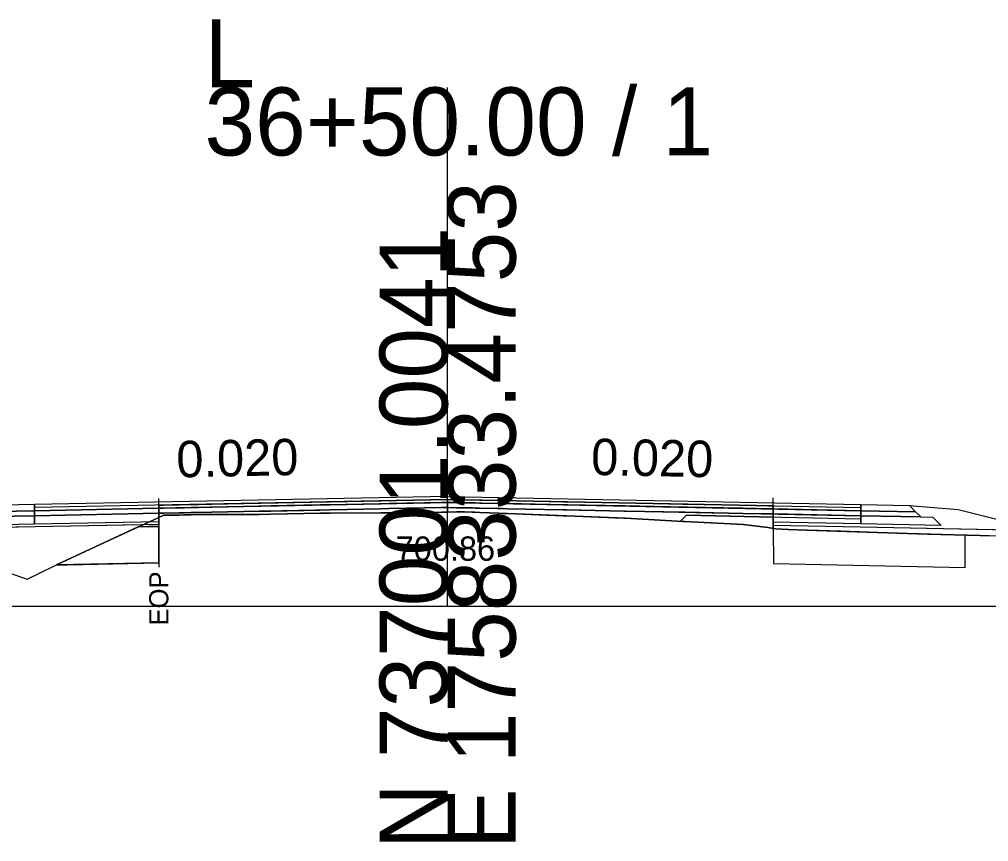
# Model space of a CAD drawing. Extents: x -26 to 4303, y -10 to 9577.
# Drawn here: x 2132.38 to 2172.26, y 6490.31 to 6524.14 of the extents above; entities that cross this region are included whole.
import ezdxf

# ---------------------------------------------------------------- set-up
doc = ezdxf.new("R2010")
doc.units = 0
for name, color, linetype in [('Exist CMT Pavement', 7, 'Continuous'), ('Old_Level_2', 7, 'Continuous'), ('Pattern 3', 7, 'Continuous'), ('Prop CMT Conc Surface', 7, 'Continuous'), ('Prop CMT Concrete Structures', 7, 'Continuous'), ('Prop CMT Pvmt Course 1', 7, 'Continuous'), ('Prop CMT Pvmt Course 1 CG', 7, 'Continuous'), ('Prop CMT Pvmt Course 1 Wedge', 7, 'Continuous'), ('Prop CMT Pvmt Course 2', 7, 'Continuous'), ('Prop CMT Pvmt Course 2 Wedge', 7, 'Continuous'), ('Prop CMT Pvmt Course 3', 7, 'Continuous'), ('Prop CMT Pvmt Surface', 7, 'Continuous'), ('Prop CMT Pvmt Surface Shoulder', 7, 'Continuous'), ('Prop CMT Pvmt Wedge Surface 1', 7, 'Continuous'), ('Prop CMT Pvmt Wedge Surface 2', 7, 'Continuous'), ('Prop CMT Pvmt Wedge Surface 3', 7, 'Continuous'), ('Prop CMT Shld Paved Course 1', 7, 'Continuous'), ('Prop CMT Shld Paved Course 2', 7, 'Continuous'), ('Prop CMT Shld Paved Course 3', 7, 'Continuous'), ('Prop CMT Slope Grass', 7, 'Continuous'), ('Prop CMT Subgrade Earthwork', 7, 'Continuous'), ('Prop Road Sect_ Recs - UC Shallow (Outline)', 7, 'Continuous'), ('Prop Shade Light', 7, 'Continuous'), ('Prop XS DDE Elevations', 7, 'Continuous'), ('Prop XS Ditch Standard Text', 7, 'Continuous'), ('Prop XS SE Text', 7, 'Continuous'), ('Prop XS Wedging', 7, 'Continuous')]:
    doc.layers.add(name, color=color, linetype=linetype)

msp = doc.modelspace()

# ---------------------------------------------------------------- linework, layer by layer
at = {"layer": 'Exist CMT Pavement'}
for points in [[(2150, 6504.515), (2133, 6504.175)], [(2150, 6504.515), (2167, 6504.175)]]:
    msp.add_lwpolyline(points, dxfattribs=at)
at = {"layer": 'Old_Level_2'}
for p, q in [((2150, 6500), (2150, 6521.342)), ((2150, 6500), (2150, 6521.342)), ((2000, 6500), (2150, 6500)), ((2000, 6500), (2150, 6500)), ((2150, 6500), (2300, 6500)), ((2150, 6500), (2300, 6500))]:
    msp.add_line(p, q, dxfattribs=at)
at = {"layer": 'Pattern 3'}
msp.add_lwpolyline([(2138.118, 6503.649), (2138.118, 6503.278), (2137.276, 6503.261), (2138.12, 6503.65)], dxfattribs=at)
at = {"layer": 'Prop CMT Conc Surface'}
for points in [[(2138.118, 6504.027), (2133, 6503.925)], [(2138.118, 6503.819), (2138.118, 6504.027)], [(2163.401, 6503.789), (2163.401, 6503.997)], [(2163.401, 6503.997), (2167, 6503.925)], [(2133, 6503.925), (2133, 6503.717)], [(2133, 6503.717), (2138.118, 6503.819)], [(2167, 6503.717), (2163.401, 6503.789)], [(2167, 6503.925), (2167, 6503.717)]]:
    msp.add_lwpolyline(points, dxfattribs=at)
at = {"layer": 'Prop CMT Concrete Structures'}
for points in [[(2150, 6504.39), (2138.118, 6504.152)], [(2150, 6504.39), (2163.401, 6504.122)], [(2133, 6503.925), (2133, 6504.175)], [(2138.118, 6504.027), (2133, 6503.925)], [(2138.118, 6504.152), (2138.118, 6504.027)], [(2163.401, 6504.122), (2163.401, 6503.997)], [(2163.401, 6503.997), (2167, 6503.925)], [(2167, 6503.925), (2167, 6504.175)]]:
    msp.add_lwpolyline(points, dxfattribs=at)
at = {"layer": 'Prop CMT Pvmt Course 1'}
for points in [[(2138.118, 6503.819), (2133, 6503.717)], [(2133, 6503.717), (2133, 6503.383)], [(2138.118, 6503.486), (2138.118, 6503.819)], [(2163.401, 6503.789), (2167, 6503.717)], [(2163.401, 6503.455), (2163.401, 6503.789)], [(2167, 6503.717), (2167, 6503.383)], [(2133, 6503.383), (2138.118, 6503.486)], [(2167, 6503.383), (2163.401, 6503.455)]]:
    msp.add_lwpolyline(points, dxfattribs=at)
at = {"layer": 'Prop CMT Pvmt Course 1 Wedge'}
for points in [[(2138.118, 6503.819), (2138.307, 6503.823), (2138.956, 6503.836), (2139.159, 6503.84), (2139.444, 6503.846), (2139.75, 6503.852), (2140.3, 6503.863), (2142.251, 6503.902), (2142.732, 6503.911), (2144.752, 6503.952), (2145.164, 6503.96), (2147.253, 6504.002), (2147.596, 6504.009), (2149.754, 6504.052), (2149.896, 6504.055), (2150, 6504.057)], [(2150, 6504.057), (2150, 6503.864)], [(2150, 6504.057), (2150.372, 6504.049), (2150.507, 6504.047), (2150.571, 6504.045), (2150.608, 6504.045), (2150.632, 6504.044), (2150.698, 6504.043), (2151.019, 6504.036), (2151.117, 6504.034), (2151.327, 6504.03), (2152.088, 6504.015), (2152.255, 6504.012), (2152.46, 6504.007), (2154.756, 6503.962), (2154.892, 6503.959), (2157.257, 6503.912), (2157.324, 6503.91), (2159.677, 6503.863), (2159.756, 6503.862), (2159.758, 6503.862), (2159.759, 6503.861), (2162.166, 6503.813), (2163.188, 6503.793), (2163.401, 6503.789)], [(2150, 6503.864), (2149.896, 6503.861), (2149.754, 6503.86), (2147.596, 6503.84), (2147.253, 6503.839), (2145.164, 6503.828), (2144.752, 6503.826), (2142.732, 6503.784), (2142.251, 6503.772), (2140.3, 6503.77), (2139.75, 6503.765), (2139.444, 6503.749), (2139.159, 6503.75), (2138.956, 6503.743), (2138.307, 6503.736), (2138.118, 6503.649)], [(2138.118, 6503.649), (2138.118, 6503.819)], [(2163.401, 6503.19), (2163.188, 6503.231), (2162.166, 6503.356), (2159.759, 6503.48), (2159.758, 6503.48), (2159.756, 6503.48), (2159.677, 6503.485), (2157.324, 6503.614), (2157.257, 6503.617), (2154.892, 6503.709), (2154.756, 6503.715), (2152.46, 6503.804), (2152.255, 6503.812), (2152.088, 6503.819), (2151.327, 6503.852), (2151.117, 6503.859), (2151.019, 6503.866), (2150.698, 6503.879), (2150.632, 6503.878), (2150.608, 6503.875), (2150.571, 6503.876), (2150.507, 6503.873), (2150.372, 6503.874), (2150, 6503.864)], [(2163.401, 6503.789), (2163.401, 6503.19)]]:
    msp.add_lwpolyline(points, dxfattribs=at)
at = {"layer": 'Prop CMT Pvmt Course 2'}
for points in [[(2133, 6504.175), (2131, 6504.135), (2130.745, 6503.88)], [(2133, 6503.925), (2133, 6504.175)], [(2167, 6504.175), (2169, 6504.135), (2169.255, 6503.88)], [(2167, 6503.925), (2167, 6504.175)], [(2130.745, 6503.88), (2133, 6503.925)], [(2169.255, 6503.88), (2167, 6503.925)]]:
    msp.add_lwpolyline(points, dxfattribs=at)
at = {"layer": 'Prop CMT Pvmt Course 2 Wedge'}
msp.add_lwpolyline([(2169, 6504.135), (2171, 6503.975), (2175.726, 6502.793)], dxfattribs=at)
at = {"layer": 'Prop CMT Pvmt Course 3'}
for points in [[(2133, 6503.925), (2130.745, 6503.88), (2130.532, 6503.667)], [(2130.532, 6503.667), (2133, 6503.717)], [(2133, 6503.717), (2133, 6503.925)], [(2167, 6503.925), (2169.255, 6503.88), (2169.468, 6503.667)], [(2167, 6503.717), (2167, 6503.925)], [(2169.468, 6503.667), (2167, 6503.717)]]:
    msp.add_lwpolyline(points, dxfattribs=at)
at = {"layer": 'Prop CMT Pvmt Surface'}
for points in [[(2150, 6504.265), (2133, 6503.925)], [(2133, 6503.925), (2133, 6504.175)], [(2150, 6504.265), (2167, 6503.925)], [(2167, 6503.925), (2167, 6504.175)]]:
    msp.add_lwpolyline(points, dxfattribs=at)
at = {"layer": 'Prop CMT Pvmt Surface Shoulder'}
for points in [[(2138.12, 6503.65), (2138.307, 6503.736), (2138.956, 6503.743), (2139.159, 6503.75), (2139.444, 6503.749), (2139.75, 6503.765), (2140.3, 6503.77), (2142.251, 6503.772), (2142.732, 6503.784), (2144.752, 6503.826), (2145.164, 6503.828), (2147.253, 6503.839), (2147.596, 6503.84), (2149.754, 6503.86), (2149.896, 6503.861), (2149.998, 6503.864)], [(2149.998, 6503.864), (2150.372, 6503.874), (2150.507, 6503.873), (2150.571, 6503.876), (2150.608, 6503.875), (2150.632, 6503.878), (2150.698, 6503.879), (2151.019, 6503.866), (2151.117, 6503.859), (2151.327, 6503.852), (2152.088, 6503.819), (2152.255, 6503.812), (2152.46, 6503.804), (2154.756, 6503.715), (2154.892, 6503.709), (2157.257, 6503.617), (2157.324, 6503.614), (2159.677, 6503.485), (2159.756, 6503.48), (2159.758, 6503.48), (2159.759, 6503.48), (2162.166, 6503.356), (2163.188, 6503.231), (2163.4, 6503.191)]]:
    msp.add_lwpolyline(points, dxfattribs=at)
at = {"layer": 'Prop CMT Pvmt Wedge Surface 1'}
for p, q in [((2133.018, 6503.258), (2125.535, 6503.109)), ((2138.117, 6503.36), (2133.018, 6503.258)), ((2163.401, 6503.33), (2166.982, 6503.258)), ((2166.982, 6503.258), (2174.465, 6503.109))]:
    msp.add_line(p, q, dxfattribs=at)
for points in [[(2138.117, 6503.36), (2138.12, 6503.65)], [(2163.401, 6503.33), (2163.4, 6503.191)]]:
    msp.add_lwpolyline(points, dxfattribs=at)
at = {"layer": 'Prop CMT Pvmt Wedge Surface 2'}
for points in [[(2138.118, 6504.152), (2138.307, 6504.156), (2138.956, 6504.169), (2139.159, 6504.173), (2139.444, 6504.179), (2139.75, 6504.185), (2140.3, 6504.196), (2142.251, 6504.235), (2142.732, 6504.245), (2144.752, 6504.285), (2145.164, 6504.293), (2147.253, 6504.335), (2147.596, 6504.342), (2149.754, 6504.385), (2149.896, 6504.388), (2150, 6504.39)], [(2150, 6504.39), (2150, 6504.265)], [(2150, 6504.39), (2150.372, 6504.383), (2150.507, 6504.38), (2150.571, 6504.379), (2150.608, 6504.378), (2150.632, 6504.377), (2150.698, 6504.376), (2151.019, 6504.37), (2151.117, 6504.368), (2151.327, 6504.363), (2152.088, 6504.348), (2152.255, 6504.345), (2152.46, 6504.341), (2154.756, 6504.295), (2154.892, 6504.292), (2157.257, 6504.245), (2157.324, 6504.244), (2159.677, 6504.196), (2159.756, 6504.195), (2159.758, 6504.195), (2159.759, 6504.195), (2162.166, 6504.147), (2163.188, 6504.126), (2163.401, 6504.122)], [(2150, 6504.265), (2149.896, 6504.263), (2149.754, 6504.26), (2147.596, 6504.217), (2147.253, 6504.21), (2145.164, 6504.168), (2144.752, 6504.16), (2142.732, 6504.12), (2142.251, 6504.11), (2140.3, 6504.071), (2139.75, 6504.06), (2139.444, 6504.054), (2139.159, 6504.048), (2138.956, 6504.044), (2138.307, 6504.031), (2138.118, 6504.027)], [(2138.118, 6504.027), (2138.118, 6504.152)], [(2163.401, 6503.997), (2163.188, 6504.001), (2162.166, 6504.022), (2159.759, 6504.07), (2159.758, 6504.07), (2159.756, 6504.07), (2159.677, 6504.071), (2157.324, 6504.119), (2157.257, 6504.12), (2154.892, 6504.167), (2154.756, 6504.17), (2152.46, 6504.216), (2152.255, 6504.22), (2152.088, 6504.223), (2151.327, 6504.238), (2151.117, 6504.243), (2151.019, 6504.245), (2150.698, 6504.251), (2150.632, 6504.252), (2150.608, 6504.253), (2150.571, 6504.254), (2150.507, 6504.255), (2150.372, 6504.258), (2150, 6504.265)], [(2163.401, 6504.122), (2163.401, 6503.997)]]:
    msp.add_lwpolyline(points, dxfattribs=at)
at = {"layer": 'Prop CMT Pvmt Wedge Surface 3'}
for points in [[(2138.118, 6504.027), (2138.307, 6504.031), (2138.956, 6504.044), (2139.159, 6504.048), (2139.444, 6504.054), (2139.75, 6504.06), (2140.3, 6504.071), (2142.251, 6504.11), (2142.732, 6504.12), (2144.752, 6504.16), (2145.164, 6504.168), (2147.253, 6504.21), (2147.596, 6504.217), (2149.754, 6504.26), (2149.896, 6504.263), (2150, 6504.265)], [(2150, 6504.057), (2149.896, 6504.055), (2149.754, 6504.052), (2147.596, 6504.009), (2147.253, 6504.002), (2145.164, 6503.96), (2144.752, 6503.952), (2142.732, 6503.911), (2142.251, 6503.902), (2140.3, 6503.863), (2139.75, 6503.852), (2139.444, 6503.846), (2139.159, 6503.84), (2138.956, 6503.836), (2138.307, 6503.823), (2138.118, 6503.819)], [(2138.118, 6503.819), (2138.118, 6504.027)], [(2150, 6504.265), (2150, 6504.057)], [(2150, 6504.265), (2150.372, 6504.258), (2150.507, 6504.255), (2150.571, 6504.254), (2150.608, 6504.253), (2150.632, 6504.252), (2150.698, 6504.251), (2151.019, 6504.245), (2151.117, 6504.243), (2151.327, 6504.238), (2152.088, 6504.223), (2152.255, 6504.22), (2152.46, 6504.216), (2154.756, 6504.17), (2154.892, 6504.167), (2157.257, 6504.12), (2157.324, 6504.118), (2159.677, 6504.071), (2159.756, 6504.07), (2159.758, 6504.07), (2159.759, 6504.07), (2162.166, 6504.022), (2163.188, 6504.001), (2163.401, 6503.997)], [(2163.401, 6503.789), (2163.188, 6503.793), (2162.166, 6503.813), (2159.759, 6503.861), (2159.758, 6503.862), (2159.756, 6503.862), (2159.677, 6503.863), (2157.324, 6503.91), (2157.257, 6503.912), (2154.892, 6503.959), (2154.756, 6503.962), (2152.46, 6504.007), (2152.255, 6504.012), (2152.088, 6504.015), (2151.327, 6504.03), (2151.117, 6504.034), (2151.019, 6504.036), (2150.698, 6504.043), (2150.632, 6504.044), (2150.608, 6504.045), (2150.571, 6504.045), (2150.507, 6504.047), (2150.372, 6504.049), (2150, 6504.057)], [(2163.401, 6503.997), (2163.401, 6503.789)]]:
    msp.add_lwpolyline(points, dxfattribs=at)
at = {"layer": 'Prop CMT Shld Paved Course 1'}
for points in [[(2133, 6503.717), (2133, 6504.175)], [(2150, 6504.057), (2133, 6503.717)], [(2150, 6504.057), (2167, 6503.717)], [(2167, 6503.717), (2167, 6504.175)]]:
    msp.add_lwpolyline(points, dxfattribs=at)
at = {"layer": 'Prop CMT Shld Paved Course 2'}
for points in [[(2133, 6504.175), (2131, 6504.135)], [(2167, 6504.175), (2169, 6504.135)]]:
    msp.add_lwpolyline(points, dxfattribs=at)
at = {"layer": 'Prop CMT Shld Paved Course 3'}
for points in [[(2150, 6504.515), (2133, 6504.175)], [(2138.118, 6504.152), (2150, 6504.39)], [(2150, 6504.265), (2150, 6504.515)], [(2150, 6504.515), (2167, 6504.175)], [(2150, 6504.39), (2150, 6504.265), (2150, 6504.265)], [(2163.401, 6504.122), (2150, 6504.39)], [(2133, 6504.175), (2133, 6503.925)], [(2133, 6503.925), (2138.118, 6504.027)], [(2138.118, 6504.027), (2138.118, 6504.152)], [(2163.401, 6503.997), (2163.401, 6504.122)], [(2167, 6503.925), (2163.401, 6503.997)], [(2167, 6504.175), (2167, 6503.925)]]:
    msp.add_lwpolyline(points, dxfattribs=at)
at = {"layer": 'Prop CMT Slope Grass'}
msp.add_lwpolyline([(2128.573, 6502.543), (2132.706, 6501.109), (2134.329, 6501.905), (2138.307, 6503.736), (2139.159, 6503.75), (2139.75, 6503.765), (2140.3, 6503.77), (2142.251, 6503.772), (2142.732, 6503.784), (2144.752, 6503.826), (2145.164, 6503.828), (2147.253, 6503.839), (2147.596, 6503.84), (2150, 6503.864), (2150.698, 6503.879), (2151.327, 6503.852), (2152.46, 6503.804), (2154.892, 6503.709), (2157.324, 6503.614), (2159.759, 6503.48), (2162.166, 6503.356), (2163.188, 6503.231), (2163.501, 6503.172), (2164.011, 6503.15), (2164.76, 6503.129), (2167.261, 6503.045), (2169.762, 6502.958), (2171.916, 6502.902), (2172.263, 6502.893)], dxfattribs=at)
at = {"layer": 'Prop CMT Subgrade Earthwork'}
for points in [[(2133, 6503.717), (2130.532, 6503.667), (2130.032, 6503.657), (2129.692, 6503.317)], [(2133, 6503.383), (2133, 6503.717)], [(2167, 6503.717), (2169.468, 6503.667), (2169.968, 6503.657), (2170.308, 6503.317)], [(2167, 6503.383), (2167, 6503.717)], [(2129.692, 6503.317), (2133, 6503.383)], [(2170.308, 6503.317), (2167, 6503.383)]]:
    msp.add_lwpolyline(points, dxfattribs=at)
at = {"layer": 'Prop Road Sect_ Recs - UC Shallow (Outline)'}
for points in [[(2138.118, 6501.778), (2133.915, 6501.702), (2137.275, 6503.261), (2138.118, 6503.278)], [(2163.402, 6501.748), (2171.294, 6501.59), (2171.297, 6502.918), (2168.438, 6503.004), (2166.179, 6503.081), (2164.34, 6503.141), (2163.4, 6503.176)]]:
    msp.add_lwpolyline(points, close=True, dxfattribs=at)
msp.add_lwpolyline([(2133.915, 6501.702), (2134.343, 6501.703), (2138.118, 6501.778)], dxfattribs=at)
at = {"layer": 'Prop Shade Light'}
for p, q in [((2138.118, 6503.282), (2137.275, 6503.261)), ((2138.118, 6501.778), (2138.118, 6503.282)), ((2163.501, 6503.172), (2163.4, 6503.191)), ((2163.4, 6503.191), (2163.402, 6501.748)), ((2164.011, 6503.15), (2163.501, 6503.172)), ((2169.762, 6502.958), (2167.261, 6503.045)), ((2171.297, 6502.918), (2169.762, 6502.958)), ((2171.294, 6501.59), (2171.297, 6502.918)), ((2133.915, 6501.702), (2138.118, 6501.778)), ((2163.402, 6501.748), (2171.294, 6501.59))]:
    msp.add_line(p, q, dxfattribs=at)
for points in [[(2137.275, 6503.261), (2137.275, 6503.261), (2133.915, 6501.702)], [(2167.261, 6503.045), (2164.76, 6503.129), (2164.011, 6503.15)]]:
    msp.add_lwpolyline(points, dxfattribs=at)
at = {"layer": 'Prop XS DDE Elevations'}
for points in [[(2138.117, 6503.36), (2137.462, 6503.347), (2138.12, 6503.65)], [(2138.956, 6503.743), (2139.159, 6503.75), (2138.307, 6503.736)], [(2139.159, 6503.75), (2139.444, 6503.749), (2139.75, 6503.765)], [(2147.596, 6503.84), (2149.754, 6503.86), (2149.896, 6503.861), (2149.998, 6503.864)], [(2149.998, 6503.864), (2150.372, 6503.874), (2150.437, 6503.874)], [(2150.507, 6503.873), (2150.571, 6503.876), (2150.437, 6503.874)], [(2150.698, 6503.879), (2151.019, 6503.866), (2151.029, 6503.865)], [(2151.029, 6503.865), (2151.117, 6503.859), (2151.327, 6503.852)], [(2152.255, 6503.812), (2152.46, 6503.804), (2151.327, 6503.852), (2152.088, 6503.819)], [(2152.46, 6503.804), (2154.756, 6503.715), (2154.892, 6503.709)], [(2157.257, 6503.617), (2157.324, 6503.614), (2154.892, 6503.709)], [(2127.709, 6502.771), (2128.573, 6502.543), (2132.706, 6501.109), (2134.329, 6501.905), (2137.462, 6503.347), (2133.018, 6503.258), (2125.535, 6503.109), (2124.724, 6502.906)], [(2166.982, 6503.258), (2174.465, 6503.109), (2175.726, 6502.793), (2174.764, 6502.831), (2174.347, 6502.847), (2172.263, 6502.893), (2171.916, 6502.902), (2169.762, 6502.958), (2167.261, 6503.045), (2164.76, 6503.129), (2164.011, 6503.15), (2163.501, 6503.172), (2163.4, 6503.191), (2163.401, 6503.33)]]:
    msp.add_lwpolyline(points, close=True, dxfattribs=at)
at = {"layer": 'Prop XS Ditch Standard Text'}
msp.add_line((2138.118, 6503.649), (2138.118, 6501.599), dxfattribs=at)
at = {"layer": 'Prop XS Wedging'}
for p, q in [((2138.118, 6503.649), (2138.118, 6504.433)), ((2163.401, 6503.33), (2163.401, 6504.451)), ((2138.119, 6504.027), (2149.995, 6504.265)), ((2138.119, 6504.152), (2138.119, 6504.027)), ((2138.119, 6504.027), (2138.12, 6503.65)), ((2149.995, 6504.265), (2150, 6504.265)), ((2150, 6504.265), (2150.005, 6504.265)), ((2150.005, 6504.265), (2163.401, 6503.997)), ((2163.401, 6503.997), (2163.401, 6504.122)), ((2163.401, 6503.664), (2163.401, 6503.997)), ((2142.251, 6503.772), (2142.732, 6503.784)), ((2142.732, 6503.784), (2144.752, 6503.826)), ((2144.752, 6503.826), (2145.164, 6503.828)), ((2145.164, 6503.828), (2147.253, 6503.839)), ((2159.833, 6503.735), (2159.578, 6503.49)), ((2159.578, 6503.49), (2159.833, 6503.735)), ((2159.833, 6503.735), (2159.578, 6503.49)), ((2159.833, 6503.735), (2163.401, 6503.664)), ((2163.401, 6503.664), (2159.833, 6503.735)), ((2163.401, 6503.33), (2163.401, 6503.664)), ((2163.188, 6503.231), (2163.4, 6503.191)), ((2163.4, 6503.191), (2163.401, 6503.33))]:
    msp.add_line(p, q, dxfattribs=at)
for points in [[(2150.002, 6504.39), (2133.002, 6504.05)], [(2150, 6504.39), (2149.998, 6504.39), (2138.119, 6504.152)], [(2149.998, 6504.39), (2166.998, 6504.05)], [(2163.401, 6504.122), (2150.002, 6504.39), (2150, 6504.39)], [(2150.005, 6504.265), (2133.005, 6503.925)], [(2150, 6504.265), (2149.995, 6504.265), (2138.119, 6504.027)], [(2149.995, 6504.265), (2166.995, 6503.925)], [(2149.995, 6504.265), (2149.995, 6504.265)], [(2163.401, 6503.997), (2150.005, 6504.265), (2150, 6504.265)], [(2150.005, 6504.265), (2150.005, 6504.265)], [(2138.12, 6503.65), (2138.307, 6503.736), (2139.159, 6503.75), (2139.75, 6503.765)], [(2139.75, 6503.765), (2140.3, 6503.77), (2142.251, 6503.772)], [(2147.253, 6503.839), (2147.596, 6503.84), (2149.754, 6503.862), (2149.896, 6503.863), (2149.998, 6503.864)], [(2149.998, 6503.864), (2150.372, 6503.874), (2150.437, 6503.874)], [(2150.437, 6503.874), (2150.507, 6503.875), (2150.571, 6503.877), (2150.608, 6503.877), (2150.632, 6503.878), (2150.698, 6503.879)], [(2150.698, 6503.879), (2151.019, 6503.866), (2151.029, 6503.865)], [(2151.029, 6503.865), (2151.117, 6503.861), (2151.327, 6503.852), (2152.088, 6503.82), (2152.255, 6503.813), (2152.46, 6503.804)], [(2152.46, 6503.804), (2154.756, 6503.715), (2154.892, 6503.709), (2157.257, 6503.617), (2157.324, 6503.614), (2159.578, 6503.49), (2159.578, 6503.49)], [(2159.833, 6503.735), (2166.988, 6503.592)], [(2159.578, 6503.49), (2159.677, 6503.485), (2159.696, 6503.484)], [(2159.696, 6503.484), (2159.756, 6503.48), (2159.759, 6503.48)], [(2159.759, 6503.48), (2162.166, 6503.356), (2163.188, 6503.231)]]:
    msp.add_lwpolyline(points, dxfattribs=at)

# ---------------------------------------------------------------- texts
at = {"layer": 'Old_Level_2'}
for s, p in [('L', (2140, 6521.342)), ('L', (2140, 6521.342)), ('36+50.00 / 1', (2140, 6518.542)), ('36+50.00 / 1', (2140, 6518.542))]:
    msp.add_text(s, height=2.8, dxfattribs=at).set_placement(p)
for s, p in [('E 1758333.4753', (2152.8, 6490)), ('E 1758333.4753', (2152.8, 6490)), ('N 737001.0041', (2150, 6490)), ('N 737001.0041', (2150, 6490))]:
    msp.add_text(s, height=2.8, rotation=90, dxfattribs=at).set_placement(p)
at = {"layer": 'Prop CMT Pvmt Course 1 CG'}
msp.add_text('700.86', height=1, dxfattribs=at).set_placement((2147.864, 6501.864))
at = {"layer": 'Prop XS Ditch Standard Text'}
msp.add_text('EOP', height=0.7874, rotation=90, dxfattribs=at).set_placement((2138.512, 6499.2))
at = {"layer": 'Prop XS SE Text'}
for rotation, p in [(1.1458, (2138.856, 6505.292)), (358.8542, (2155.896, 6505.397))]:
    msp.add_text('0.020', height=1.5, rotation=rotation, dxfattribs=at).set_placement(p)

doc.saveas('drawing.dxf')
